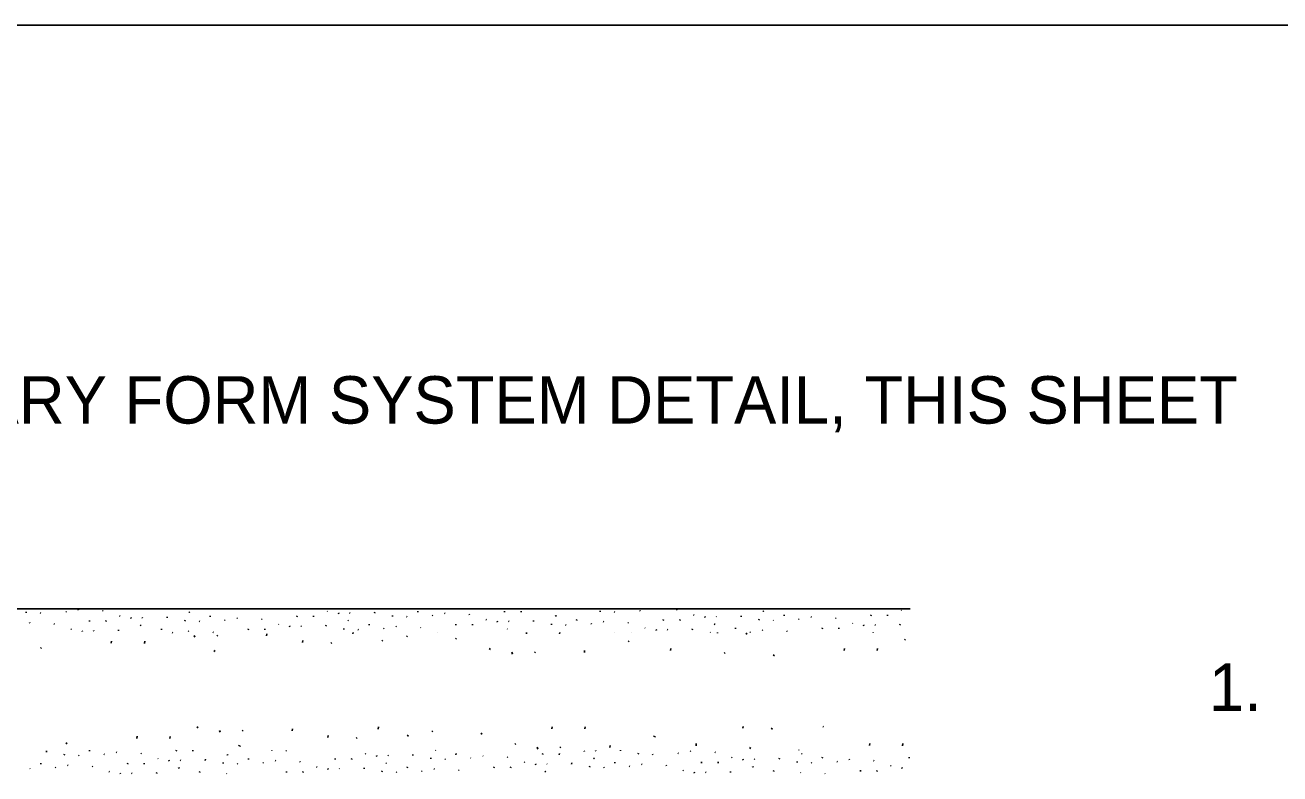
# Model space of a CAD drawing. Extents: x 99862 to 103151, y 100000 to 111076.
# Drawn here: x 100425.5 to 100849, y 110822.9 to 111075.5 of the extents above; entities that cross this region are included whole.
import ezdxf

# ---------------------------------------------------------------- set-up
doc = ezdxf.new("R2010")
doc.units = 0
for name, color, linetype in [('Level 1', 7, 'Continuous'), ('Level 11', 7, 'Continuous'), ('Level 18', 7, 'Continuous'), ('Level 20', 7, 'Continuous')]:
    doc.layers.add(name, color=color, linetype=linetype)

msp = doc.modelspace()

# ---------------------------------------------------------------- linework, layer by layer
at = {"layer": 'Level 1'}
msp.add_lwpolyline([(99862, 108999.5), (103151, 108999.5), (103151, 111075.5), (99862, 111075.5)], close=True, dxfattribs=at)
at = {"layer": 'Level 11'}
msp.add_line((100165.98, 110878.54), (100724.21, 110878.54), dxfattribs=at)
at = {"layer": 'Level 18'}
for p, q in [((100425.88, 110877.26), (100425.94, 110877.6)), ((100430.66, 110877.26), (100430.86, 110877.1)), ((100439.27, 110877.65), (100439.47, 110877.48)), ((100443.43, 110878.36), (100443.62, 110878.19)), ((100451.72, 110877.97), (100451.91, 110877.8)), ((100480.82, 110877.53), (100481.02, 110877.36)), ((100480.98, 110877.49), (100481.18, 110877.32)), ((100527.44, 110877.82), (100527.63, 110877.65)), ((100531.25, 110877.2), (100531.36, 110876.9)), ((100535.05, 110877.25), (100535.25, 110877.08)), ((100543.48, 110877.14), (100543.54, 110877.49)), ((100558.03, 110877.47), (100558.09, 110877.81)), ((100567.06, 110877.14), (100567.26, 110876.97)), ((100575.35, 110876.74), (100575.54, 110876.58)), ((100587.3, 110877.48), (100587.36, 110877.82)), ((100592.89, 110877.47), (100592.95, 110877.81)), ((100619.55, 110877.62), (100619.61, 110877.96)), ((100624.33, 110877.62), (100624.53, 110877.46)), ((100632.94, 110878.01), (100633.14, 110877.84)), ((100645.39, 110878.33), (100645.58, 110878.16)), ((100674.5, 110877.89), (100674.69, 110877.72)), ((100674.65, 110877.85), (100674.85, 110877.68)), ((100721.11, 110878.18), (100721.31, 110878.01)), ((100426.99, 110873.96), (100427.19, 110873.79)), ((100435.28, 110873.57), (100435.47, 110873.4)), ((100447.23, 110874.3), (100447.29, 110874.65)), ((100452.82, 110874.29), (100452.88, 110874.64)), ((100457.41, 110876.23), (100457.6, 110876.06)), ((100461.21, 110875.62), (100461.33, 110875.32)), ((100464.39, 110873.12), (100464.58, 110872.96)), ((100464.55, 110873.08), (100464.74, 110872.91)), ((100465.02, 110875.66), (100465.21, 110875.49)), ((100473.45, 110875.55), (100473.5, 110875.9)), ((100479.48, 110874.44), (100479.54, 110874.79)), ((100484.26, 110874.45), (100484.46, 110874.28)), ((100488, 110875.88), (100488.05, 110876.22)), ((100492.87, 110874.83), (100493.07, 110874.66)), ((100497.03, 110875.55), (100497.22, 110875.38)), ((100505.32, 110875.16), (100505.51, 110874.99)), ((100511.01, 110873.42), (100511.2, 110873.25)), ((100514.81, 110872.8), (100514.93, 110872.5)), ((100517.27, 110875.89), (100517.32, 110876.23)), ((100518.62, 110872.84), (100518.81, 110872.67)), ((100522.86, 110875.88), (100522.91, 110876.23)), ((100527.05, 110872.74), (100527.1, 110873.08)), ((100534.42, 110874.71), (100534.62, 110874.54)), ((100541.6, 110873.06), (100541.65, 110873.41)), ((100549.52, 110876.03), (100549.57, 110876.38)), ((100550.63, 110872.73), (100550.82, 110872.56)), ((100554.3, 110876.04), (100554.49, 110875.87)), ((100562.91, 110876.42), (100563.1, 110876.25)), ((100570.87, 110873.07), (100570.92, 110873.42)), ((100576.46, 110873.06), (100576.51, 110873.41)), ((100581.04, 110875), (100581.23, 110874.84)), ((100584.85, 110874.39), (100584.96, 110874.09)), ((100588.65, 110874.43), (100588.85, 110874.26)), ((100597.08, 110874.32), (100597.14, 110874.67)), ((100603.12, 110873.21), (100603.17, 110873.56)), ((100604.46, 110876.3), (100604.65, 110876.13)), ((100604.62, 110876.26), (100604.81, 110876.09)), ((100607.9, 110873.22), (100608.09, 110873.05)), ((100611.63, 110874.65), (100611.69, 110875)), ((100616.51, 110873.6), (100616.7, 110873.44)), ((100620.66, 110874.32), (100620.86, 110874.15)), ((100628.95, 110873.93), (100629.14, 110873.76)), ((100640.9, 110874.66), (100640.96, 110875.01)), ((100646.49, 110874.65), (100646.55, 110875)), ((100651.08, 110876.59), (100651.27, 110876.42)), ((100654.88, 110875.98), (100655, 110875.68)), ((100658.06, 110873.48), (100658.25, 110873.32)), ((100658.22, 110873.44), (100658.41, 110873.27)), ((100658.69, 110876.02), (100658.88, 110875.85)), ((100667.12, 110875.91), (100667.17, 110876.26)), ((100673.15, 110874.8), (100673.21, 110875.15)), ((100677.93, 110874.81), (100678.13, 110874.64)), ((100681.67, 110876.24), (100681.72, 110876.58)), ((100686.54, 110875.19), (100686.74, 110875.02)), ((100690.7, 110875.91), (100690.89, 110875.74)), ((100698.99, 110875.52), (100699.18, 110875.35)), ((100704.68, 110873.78), (100704.87, 110873.61)), ((100708.48, 110873.16), (100708.6, 110872.86)), ((100710.94, 110876.25), (100710.99, 110876.59)), ((100712.29, 110873.2), (100712.48, 110873.04)), ((100716.53, 110876.24), (100716.58, 110876.59)), ((100720.72, 110873.1), (100720.77, 110873.44)), ((100440.97, 110871.83), (100441.16, 110871.66)), ((100444.78, 110871.21), (100444.89, 110870.91)), ((100448.58, 110871.26), (100448.78, 110871.09)), ((100457.01, 110871.15), (100457.07, 110871.49)), ((100471.56, 110871.47), (100471.62, 110871.82)), ((100475.22, 110870.59), (100475.35, 110870.48)), ((100480.59, 110871.14), (100480.79, 110870.97)), ((100482.58, 110869.58), (100482.81, 110868.98)), ((100488.88, 110870.75), (100489.07, 110870.59)), ((100490.19, 110869.67), (100490.57, 110869.33)), ((100500.83, 110871.49), (100500.89, 110871.83)), ((100506.42, 110871.48), (100506.48, 110871.82)), ((100507.05, 110869.45), (100507.16, 110870.15)), ((100533.08, 110871.63), (100533.14, 110871.97)), ((100536.15, 110870.11), (100536.22, 110870.59)), ((100537.86, 110871.63), (100538.06, 110871.46)), ((100546.47, 110872.02), (100546.67, 110871.85)), ((100554.21, 110869.45), (100554.59, 110869.11)), ((100558.92, 110872.34), (100559.11, 110872.17)), ((100564.61, 110870.6), (100564.62, 110870.59)), ((100570.79, 110868.66), (100571.17, 110868.33)), ((100588.18, 110871.86), (100588.38, 110871.69)), ((100594.69, 110870.13), (100594.76, 110870.59)), ((100605.87, 110870.11), (100605.95, 110870.59)), ((100624.52, 110870.59), (100624.52, 110870.6)), ((100630.11, 110870.59), (100630.11, 110870.59)), ((100634.64, 110872.19), (100634.83, 110872.02)), ((100638.45, 110871.57), (100638.56, 110871.27)), ((100642.25, 110871.62), (100642.45, 110871.45)), ((100650.68, 110871.51), (100650.74, 110871.85)), ((100656.75, 110870.59), (100656.77, 110870.74)), ((100659.19, 110870.41), (100659.22, 110870.59)), ((100665.23, 110871.84), (100665.29, 110872.18)), ((100668.75, 110870.42), (100669.14, 110870.09)), ((100670.11, 110870.79), (100670.3, 110870.62)), ((100674.26, 110871.5), (100674.46, 110871.33)), ((100682.55, 110871.11), (100682.74, 110870.94)), ((100694.5, 110871.85), (100694.56, 110872.19)), ((100700.09, 110871.84), (100700.15, 110872.18)), ((100711.66, 110870.67), (100711.75, 110870.59)), ((100711.82, 110870.63), (100711.86, 110870.59)), ((100722.24, 110868.36), (100722.62, 110868.02)), ((100430.72, 110865.49), (100431.1, 110865.15)), ((100454.62, 110866.95), (100454.73, 110867.64)), ((100465.8, 110866.93), (100465.91, 110867.63)), ((100489.25, 110864.52), (100489.63, 110864.18)), ((100519.12, 110867.24), (100519.23, 110867.93)), ((100528.68, 110867.25), (100529.07, 110866.91)), ((100545.9, 110868.01), (100546.29, 110867.68)), ((100582.17, 110865.18), (100582.55, 110864.85)), ((100597.39, 110864.04), (100597.77, 110863.7)), ((100614.25, 110863.82), (100614.36, 110864.51)), ((100629, 110867.78), (100629.39, 110867.44)), ((100643.35, 110864.48), (100643.46, 110865.17)), ((100701.89, 110864.5), (100702, 110865.19)), ((100713.07, 110864.48), (100713.18, 110865.17)), ((100589.78, 110863.95), (100590.01, 110863.35)), ((100661.41, 110863.81), (100661.79, 110863.48)), ((100677.99, 110863.03), (100678.37, 110862.69)), ((100483.55, 110838.76), (100483.94, 110838.42)), ((100544.74, 110838.05), (100544.84, 110838.74)), ((100603.28, 110838.07), (100603.39, 110838.77)), ((100614.46, 110838.06), (100614.57, 110838.75)), ((100667.78, 110838.36), (100667.87, 110838.94)), ((100694.78, 110838.94), (100694.95, 110838.8)), ((100463.21, 110834.9), (100463.31, 110835.59)), ((100474.39, 110834.88), (100474.5, 110835.57)), ((100491.17, 110837.53), (100491.4, 110836.93)), ((100498.78, 110837.62), (100499.16, 110837.28)), ((100515.64, 110837.4), (100515.75, 110838.09)), ((100527.71, 110835.18), (100527.81, 110835.87)), ((100537.27, 110835.19), (100537.65, 110834.86)), ((100554.49, 110835.96), (100554.87, 110835.62)), ((100562.8, 110837.39), (100563.18, 110837.05)), ((100579.38, 110836.61), (100579.76, 110836.27)), ((100637.59, 110835.72), (100637.98, 110835.38)), ((100637.91, 110835.64), (100638.29, 110835.3)), ((100677.34, 110838.37), (100677.73, 110838.03)), ((100432.73, 110830.29), (100432.79, 110830.63)), ((100439.3, 110833.43), (100439.69, 110833.1)), ((100447.28, 110830.61), (100447.33, 110830.91)), ((100456.31, 110830.28), (100456.5, 110830.11)), ((100476.55, 110830.62), (100476.6, 110830.92)), ((100482.14, 110830.61), (100482.19, 110830.92)), ((100497.52, 110832.55), (100497.91, 110832.21)), ((100497.84, 110832.46), (100498.22, 110832.12)), ((100508.8, 110830.76), (100508.82, 110830.92)), ((100513.58, 110830.77), (100513.77, 110830.6)), ((100563.87, 110830.93), (100563.94, 110830.87)), ((100563.98, 110830.93), (100564.09, 110830.82)), ((100590.76, 110833.13), (100591.14, 110832.79)), ((100598.37, 110831.9), (100598.6, 110831.3)), ((100605.98, 110831.98), (100606.36, 110831.65)), ((100614.17, 110830.71), (100614.28, 110830.41)), ((100617.97, 110830.75), (100618.16, 110830.59)), ((100622.84, 110831.77), (100622.95, 110832.46)), ((100626.4, 110830.65), (100626.45, 110830.94)), ((100649.98, 110830.64), (100650.17, 110830.47)), ((100651.94, 110832.42), (100652.04, 110833.11)), ((100658.27, 110830.25), (100658.46, 110830.08)), ((100670, 110831.76), (100670.38, 110831.42)), ((100686.58, 110830.98), (100686.62, 110830.94)), ((100710.48, 110832.44), (100710.59, 110833.13)), ((100721.66, 110832.42), (100721.77, 110833.11)), ((100430.84, 110826.21), (100430.9, 110826.55)), ((100438.76, 110829.18), (100438.82, 110829.52)), ((100439.88, 110825.88), (100440.07, 110825.71)), ((100443.55, 110829.18), (100443.74, 110829.01)), ((100452.16, 110829.57), (100452.35, 110829.4)), ((100460.12, 110826.22), (100460.17, 110826.56)), ((100464.6, 110829.89), (100464.79, 110829.72)), ((100465.71, 110826.21), (100465.76, 110826.56)), ((100470.29, 110828.15), (100470.48, 110827.98)), ((100474.1, 110827.53), (100474.21, 110827.23)), ((100477.9, 110827.58), (100478.09, 110827.41)), ((100486.33, 110827.47), (100486.39, 110827.82)), ((100492.36, 110826.36), (100492.42, 110826.71)), ((100493.71, 110829.45), (100493.9, 110829.28)), ((100493.87, 110829.41), (100494.06, 110829.24)), ((100497.15, 110826.37), (100497.34, 110826.2)), ((100500.88, 110827.8), (100500.93, 110828.14)), ((100505.76, 110826.75), (100505.95, 110826.58)), ((100509.91, 110827.47), (100510.1, 110827.3)), ((100518.2, 110827.07), (100518.39, 110826.91)), ((100530.15, 110827.81), (100530.21, 110828.15)), ((100535.74, 110827.8), (100535.8, 110828.14)), ((100540.33, 110829.74), (100540.52, 110829.57)), ((100544.13, 110829.12), (100544.25, 110828.82)), ((100547.31, 110826.63), (100547.5, 110826.46)), ((100547.94, 110829.17), (100548.13, 110829)), ((100556.37, 110829.06), (100556.42, 110829.4)), ((100562.4, 110827.95), (100562.45, 110828.29)), ((100567.18, 110827.95), (100567.37, 110827.79)), ((100570.92, 110829.38), (100570.97, 110829.73)), ((100575.79, 110828.34), (100575.99, 110828.17)), ((100579.95, 110829.05), (100580.14, 110828.88)), ((100588.24, 110828.66), (100588.43, 110828.49)), ((100593.93, 110826.92), (100594.12, 110826.75)), ((100597.73, 110826.31), (100597.85, 110826.01)), ((100600.19, 110829.4), (100600.24, 110829.74)), ((100601.54, 110826.35), (100601.73, 110826.18)), ((100605.78, 110829.39), (100605.83, 110829.73)), ((100609.97, 110826.24), (100610.02, 110826.59)), ((100617.34, 110828.22), (100617.54, 110828.05)), ((100617.5, 110828.18), (100617.69, 110828.01)), ((100624.52, 110826.57), (100624.57, 110826.91)), ((100632.44, 110829.54), (100632.49, 110829.88)), ((100633.55, 110826.24), (100633.74, 110826.07)), ((100637.22, 110829.54), (100637.41, 110829.37)), ((100645.83, 110829.93), (100646.02, 110829.76)), ((100653.79, 110826.58), (100653.84, 110826.92)), ((100659.38, 110826.57), (100659.43, 110826.92)), ((100663.96, 110828.51), (100664.15, 110828.34)), ((100667.77, 110827.89), (100667.88, 110827.59)), ((100671.57, 110827.94), (100671.76, 110827.77)), ((100680, 110827.83), (100680.06, 110828.18)), ((100686.04, 110826.72), (100686.09, 110827.07)), ((100687.54, 110829.77), (100687.73, 110829.6)), ((100690.82, 110826.73), (100691.01, 110826.56)), ((100694.55, 110828.16), (100694.61, 110828.5)), ((100699.43, 110827.11), (100699.62, 110826.94)), ((100703.58, 110827.83), (100703.77, 110827.66)), ((100711.87, 110827.44), (100712.06, 110827.27)), ((100723.82, 110828.17), (100723.88, 110828.51)), ((100427.11, 110824.78), (100427.3, 110824.61)), ((100435.72, 110825.16), (100435.91, 110824.99)), ((100448.16, 110825.49), (100448.36, 110825.32)), ((100453.85, 110823.75), (100454.05, 110823.58)), ((100457.66, 110823.13), (100457.74, 110822.91)), ((100461.47, 110823.17), (100461.66, 110823.01)), ((100469.9, 110823.07), (100469.95, 110823.41)), ((100477.27, 110825.04), (100477.47, 110824.87)), ((100477.43, 110825), (100477.62, 110824.83)), ((100484.44, 110823.39), (100484.5, 110823.74)), ((100493.48, 110823.06), (100493.64, 110822.92)), ((100513.72, 110823.4), (100513.77, 110823.75)), ((100519.31, 110823.39), (100519.36, 110823.74)), ((100523.89, 110825.33), (100524.08, 110825.17)), ((100527.7, 110824.72), (100527.81, 110824.42)), ((100531.5, 110824.76), (100531.69, 110824.59)), ((100539.93, 110824.65), (100539.99, 110825)), ((100545.97, 110823.55), (100546.02, 110823.89)), ((100550.75, 110823.55), (100550.94, 110823.38)), ((100554.48, 110824.98), (100554.53, 110825.33)), ((100559.36, 110823.93), (100559.55, 110823.77)), ((100563.51, 110824.65), (100563.7, 110824.48)), ((100571.8, 110824.26), (100571.99, 110824.09)), ((100583.75, 110824.99), (100583.81, 110825.34)), ((100589.34, 110824.98), (100589.4, 110825.33)), ((100600.91, 110823.82), (100601.1, 110823.65)), ((100601.07, 110823.77), (100601.26, 110823.6)), ((100616, 110825.13), (100616.06, 110825.48)), ((100620.78, 110825.14), (100620.98, 110824.97)), ((100629.39, 110825.52), (100629.59, 110825.35)), ((100641.84, 110825.85), (100642.03, 110825.68)), ((100647.53, 110824.11), (100647.72, 110823.94)), ((100651.33, 110823.49), (100651.45, 110823.19)), ((100655.14, 110823.53), (100655.33, 110823.37)), ((100663.57, 110823.43), (100663.62, 110823.77)), ((100670.94, 110825.4), (100671.14, 110825.23)), ((100671.1, 110825.36), (100671.29, 110825.19)), ((100678.12, 110823.75), (100678.17, 110824.1)), ((100687.15, 110823.42), (100687.34, 110823.25)), ((100695.44, 110823.03), (100695.53, 110822.94)), ((100707.39, 110823.76), (100707.44, 110824.11)), ((100712.98, 110823.75), (100713.03, 110824.1)), ((100717.56, 110825.69), (100717.75, 110825.53)), ((100721.37, 110825.08), (100721.48, 110824.78))]:
    msp.add_line(p, q, dxfattribs=at)

# ---------------------------------------------------------------- texts
at = {"layer": 'Level 20'}
for s, p in [('SEE TEMPORARY FORM SYSTEM DETAIL, THIS SHEET', (100268.9, 110941.07)), ('1.', (100824.99, 110844.16))]:
    msp.add_text(s, height=16, dxfattribs=at).set_placement(p)

doc.saveas('drawing.dxf')
